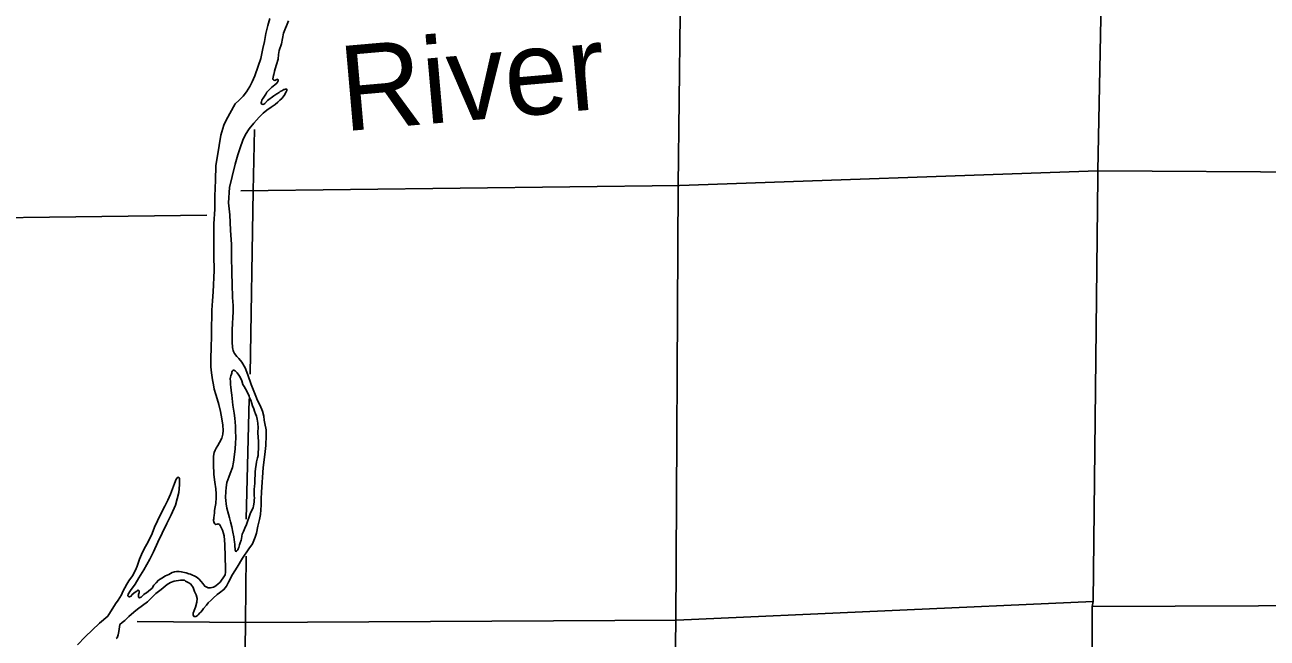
# Model space of a CAD drawing. Extents: x 369523 to 838377, y 495025 to 936819.
# Drawn here: x 626332 to 641756, y 838052 to 845664 of the extents above; entities that cross this region are included whole.
import ezdxf

# ---------------------------------------------------------------- set-up
doc = ezdxf.new("R2010")
doc.units = 0
for name, color, linetype in [('Level 10', 7, 'Continuous'), ('Level 15', 7, 'Continuous'), ('Level 22', 7, 'Continuous')]:
    doc.layers.add(name, color=color, linetype=linetype)

msp = doc.modelspace()

# ---------------------------------------------------------------- linework, layer by layer
at = {"layer": 'Level 10'}
for points in [[(629372, 845744), (629347, 845656), (629324, 845558), (629308, 845457), (629287, 845369), (629260, 845247), (629227, 845152), (629188, 845030), (629153, 844955), (629127, 844897), (629082, 844833), (629044, 844778), (628991, 844730), (628945, 844685), (628876, 844564), (628827, 844474), (628804, 844418), (628765, 844293), (628744, 844165), (628704, 843914), (628698, 843738), (628691, 843539), (628689, 843375), (628680, 843193), (628678, 843002), (628679, 842800), (628681, 842614), (628671, 842349), (628660, 842237), (628655, 842121), (628654, 842019), (628650, 841943), (628649, 841857), (628648, 841760), (628646, 841700), (628645, 841626), (628642, 841558), (628640, 841502), (628640, 841460), (628641, 841424), (628643, 841380), (628654, 841318), (628662, 841260), (628672, 841198), (628683, 841144), (628701, 841076), (628720, 841022), (628740, 840952), (628759, 840866), (628778, 840772), (628790, 840696), (628795, 840628), (628791, 840584), (628776, 840534), (628748, 840481), (628727, 840445), (628705, 840409), (628693, 840385), (628681, 840355), (628674, 840309), (628674, 840262), (628675, 840210), (628680, 840082), (628692, 839986), (628703, 839904), (628706, 839842), (628708, 839798), (628703, 839724), (628691, 839662), (628687, 839630)], [(629604, 845712), (629543, 845560), (629518, 845427), (629491, 845345), (629483, 845297), (629478, 845239), (629457, 845170), (629441, 845118), (629431, 845090), (629426, 845062), (629424, 845056), (629422, 845046), (629420, 845034), (629416, 845014), (629412, 844994), (629414, 844984), (629424, 844976), (629436, 844974), (629454, 844982), (629470, 844990), (629474, 844986), (629478, 844982), (629476, 844968), (629470, 844954), (629460, 844942), (629435, 844920), (629415, 844902), (629395, 844887), (629367, 844859), (629353, 844847), (629338, 844827), (629324, 844805), (629306, 844778), (629290, 844754), (629280, 844738), (629276, 844728), (629271, 844710), (629267, 844696), (629267, 844690), (629269, 844682), (629277, 844678), (629287, 844676), (629297, 844680), (629299, 844680), (629311, 844690)], [(629311, 844690), (629344, 844725), (629424, 844785), (629460, 844808), (629489, 844826), (629503, 844838), (629521, 844844), (629549, 844861), (629557, 844863), (629569, 844865), (629577, 844867), (629583, 844867), (629583, 844865), (629583, 844849), (629577, 844833), (629552, 844789), (629522, 844752), (629498, 844728), (629472, 844704), (629439, 844675), (629389, 844643), (629337, 844604), (629292, 844566), (629242, 844519), (629173, 844445), (629116, 844374), (629070, 844302), (629037, 844233), (629004, 844137), (628977, 844049), (628942, 843934), (628905, 843780), (628874, 843647), (628860, 843457), (628875, 843307), (628886, 843116), (628896, 842936), (628899, 842796), (628901, 842580), (628906, 842444), (628911, 842281), (628920, 842181), (628917, 842101), (628915, 842031), (628910, 841959), (628907, 841879), (628905, 841821), (628905, 841787), (628904, 841749), (628906, 841703), (628908, 841683), (628910, 841659), (628912, 841639), (628919, 841621), (628923, 841609), (628933, 841585), (628965, 841549), (628987, 841523), (629024, 841479), (629068, 841408), (629099, 841320), (629140, 841200), (629166, 841136), (629199, 841056), (629221, 841000), (629254, 840938), (629282, 840871), (629297, 840805), (629305, 840759), (629313, 840715), (629326, 840637), (629327, 840569), (629324, 840444), (629313, 840330), (629290, 840170), (629268, 839863), (629267, 839781), (629264, 839701), (629257, 839587), (629245, 839524), (629226, 839442), (629209, 839354), (629193, 839306), (629158, 839221), (629113, 839159), (629034, 839044), (628967, 838933), (628911, 838842), (628862, 838748), (628837, 838696), (628803, 838655), (628750, 838613), (628720, 838592), (628670, 838548), (628643, 838522), (628609, 838491), (628585, 838463), (628551, 838421), (628534, 838395), (628518, 838376), (628504, 838364)], [(628946, 840683), (628937, 840783), (628931, 840844), (628914, 840944), (628906, 841026), (628901, 841066), (628895, 841124), (628888, 841172), (628886, 841196), (628886, 841210), (628884, 841238), (628882, 841272), (628887, 841290), (628889, 841308), (628899, 841330), (628901, 841340), (628903, 841352), (628907, 841364), (628913, 841372), (628921, 841376), (628927, 841376), (628933, 841372), (628943, 841370), (628955, 841358), (628967, 841343), (628987, 841317), (629003, 841293), (629024, 841247), (629040, 841201), (629054, 841175), (629070, 841147), (629086, 841119), (629115, 841057), (629123, 841033), (629137, 841004), (629150, 840966), (629160, 840934), (629174, 840900), (629184, 840868), (629197, 840838), (629207, 840808), (629217, 840770), (629226, 840720), (629228, 840664), (629224, 840614), (629229, 840532), (629231, 840504), (629234, 840458), (629234, 840399), (629230, 840359), (629227, 840319), (629219, 840289), (629207, 840241), (629202, 840203), (629196, 840159), (629191, 840111), (629191, 840067), (629189, 840037), (629186, 839976), (629184, 839936), (629180, 839900), (629177, 839856), (629179, 839820), (629181, 839792), (629179, 839766), (629180, 839740), (629176, 839720), (629170, 839692), (629166, 839674), (629129, 839595), (629082, 839461)], [(629082, 839461), (629064, 839415), (629045, 839376), (629031, 839342), (629025, 839316), (629020, 839286), (629016, 839268), (629006, 839234), (628998, 839212), (628992, 839192), (628989, 839178), (628983, 839168), (628981, 839160), (628975, 839149), (628969, 839139), (628965, 839137), (628959, 839131), (628951, 839129), (628947, 839135), (628943, 839147), (628943, 839159), (628939, 839191), (628938, 839219), (628934, 839245), (628928, 839309), (628913, 839367), (628901, 839435), (628884, 839497), (628872, 839547), (628861, 839591), (628841, 839667), (628832, 839717), (628826, 839761), (628824, 839799), (628827, 839871), (628831, 839923), (628840, 839982), (628864, 840048), (628881, 840096), (628909, 840168), (628922, 840237), (628933, 840331), (628941, 840401), (628948, 840473), (628951, 840537), (628947, 840631), (628946, 840683)], [(628223, 839780), (628242, 839860), (628253, 839954), (628253, 840005), (628251, 840039), (628247, 840043), (628231, 840048), (628211, 840026), (628189, 839970), (628141, 839837), (628107, 839763), (628070, 839689), (628021, 839594), (627978, 839507), (627940, 839429), (627911, 839349), (627880, 839282), (627848, 839220), (627815, 839160), (627781, 839089), (627754, 839033), (627725, 838944), (627705, 838896), (627668, 838826), (627622, 838763), (627597, 838721), (627571, 838675), (627549, 838629), (627530, 838590), (627490, 838524), (627459, 838476), (627360, 838324), (627257, 838239), (627079, 838070), (626986, 837969)], [(628687, 839630), (628686, 839604), (628682, 839578), (628680, 839546), (628678, 839531), (628676, 839519), (628676, 839509), (628678, 839501), (628678, 839495), (628681, 839485), (628689, 839471), (628699, 839462), (628719, 839468), (628733, 839472), (628747, 839462), (628755, 839450), (628759, 839442), (628775, 839416), (628787, 839390), (628799, 839352), (628806, 839320), (628812, 839266), (628815, 839214), (628821, 838912), (628823, 838870), (628818, 838836), (628796, 838801), (628774, 838773), (628755, 838745), (628729, 838723), (628709, 838705), (628689, 838694), (628673, 838686), (628655, 838680), (628635, 838676), (628607, 838678), (628565, 838697), (628541, 838729), (628521, 838755), (628491, 838787), (628458, 838811), (628390, 838844), (628368, 838852), (628334, 838864), (628274, 838875), (628246, 838879), (628216, 838879), (628188, 838874), (628162, 838866), (628121, 838842), (628079, 838825), (628031, 838797), (627992, 838773), (627962, 838740), (627934, 838708), (627912, 838672), (627865, 838633), (627841, 838615), (627825, 838605), (627809, 838593), (627797, 838583), (627784, 838570), (627774, 838562), (627762, 838556), (627754, 838554), (627748, 838558), (627744, 838564), (627742, 838570), (627742, 838580), (627743, 838592), (627745, 838604), (627749, 838612), (627751, 838626), (627749, 838634), (627749, 838638), (627737, 838646), (627731, 838642), (627721, 838636), (627715, 838632), (627709, 838628), (627701, 838622), (627685, 838610), (627662, 838589), (627650, 838573), (627640, 838569), (627630, 838563), (627618, 838567), (627612, 838577), (627616, 838599), (627643, 838643), (627700, 838720), (627746, 838802), (627809, 838899), (627884, 839034), (627927, 839122), (627982, 839243), (628037, 839356), (628096, 839476), (628147, 839583), (628202, 839704), (628223, 839780)], [(628504, 838364), (628482, 838340), (628470, 838328), (628464, 838326), (628454, 838320), (628451, 838318), (628449, 838318), (628439, 838320), (628431, 838322), (628426, 838328), (628420, 838340), (628420, 838362), (628432, 838396), (628450, 838438), (628469, 838498), (628471, 838542), (628458, 838588), (628440, 838632), (628420, 838680), (628393, 838722), (628369, 838740), (628327, 838761), (628313, 838771), (628263, 838771), (628187, 838758), (628138, 838744), (628100, 838717), (628026, 838655), (627957, 838606), (627917, 838566), (627854, 838503), (627731, 838410), (627685, 838375), (627622, 838319), (627574, 838272), (627541, 838248), (627513, 838222), (627505, 838194), (627498, 838133), (627490, 838093), (627476, 838057), (627466, 838049)]]:
    msp.add_lwpolyline(points, dxfattribs=at)
at = {"layer": 'Level 15'}
msp.add_lwpolyline([(639955, 858199), (639904, 854661), (639760, 849324), (639655, 843854), (639655, 843777), (639597, 838505), (639585, 838445), (639605, 833180), (639591, 830635)], dxfattribs=at)
at = {"layer": 'Level 22'}
for points in [[(634611, 852654), (634505, 848971), (634445, 843671), (634413, 838233), (634315, 833014), (634239, 828775)], [(629129, 841328), (629166, 843606), (629182, 844365)], [(629012, 843606), (634459, 843669), (639655, 843854)], [(645043, 843819), (639655, 843854)], [(628593, 843302), (624029, 843245), (620861, 843366)], [(629078, 839527), (629117, 841021)], [(628898, 827632), (629008, 832961), (629070, 838259), (629079, 839070)], [(639597, 838505), (634423, 838275), (629076, 838245), (627726, 838258)], [(644743, 838465), (639585, 838445)]]:
    msp.add_lwpolyline(points, dxfattribs=at)

# ---------------------------------------------------------------- texts
at = {"layer": 'Level 10'}
msp.add_text('River', height=1056, rotation=5, dxfattribs=at).set_placement((630293, 844342))

doc.saveas('drawing.dxf')
